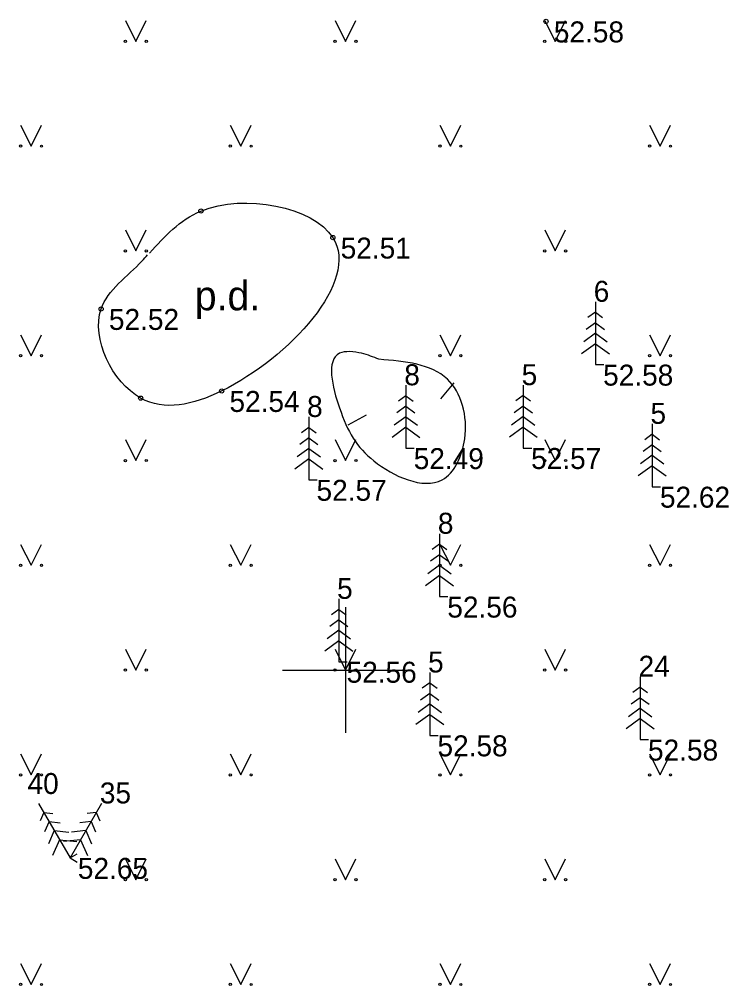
# Model space of a CAD drawing. Extents: x 619806 to 620082, y 405176 to 405386.
# Drawn here: x 619992.22 to 620009.14, y 405242.47 to 405265.53 of the extents above; entities that cross this region are included whole.
import ezdxf

# ---------------------------------------------------------------- set-up
doc = ezdxf.new("R2010")
doc.units = 0
for name, color, linetype in [('GEOD_ELEM_####_####_#', 7, 'Continuous'), ('RELJ_AATZ_####_TKST_#', 7, 'Continuous'), ('RELJ_ELEM_####_####_#', 7, 'Continuous'), ('RELJ_HORZ_PAMT_####_#', 7, 'Continuous'), ('TERT_DIAM_####_TKST_#', 7, 'Continuous'), ('TERT_ELEM_####_####_#', 7, 'Continuous'), ('TERT_IZMT_####_TKST_#', 7, 'Continuous'), ('TERT_KONT_####_####_#', 7, 'Continuous')]:
    doc.layers.add(name, color=color, linetype=linetype)

msp = doc.modelspace()

# ---------------------------------------------------------------- linework, layer by layer
at = {"layer": 'GEOD_ELEM_####_####_#'}
for p, q in [((620000, 405251.5), (620000, 405250)), ((619998.5, 405250), (620000, 405250)), ((620000, 405250), (620000, 405248.5)), ((620000, 405250), (620001.5, 405250))]:
    msp.add_line(p, q, dxfattribs=at)
at = {"layer": 'RELJ_ELEM_####_####_#'}
for centre in [(620004.782, 405265.475), (619996.552, 405260.952), (619999.699, 405260.318), (619994.172, 405258.616), (619997.047, 405256.659), (619995.114, 405256.488)]:
    msp.add_circle(centre, 0.05, dxfattribs=at)
at = {"layer": 'RELJ_HORZ_PAMT_####_#'}
for p, q in [((620002.276, 405256.47), (620002.593, 405256.856)), ((620000.493, 405256.08), (620000.052, 405255.845))]:
    msp.add_line(p, q, dxfattribs=at)
msp.add_spline([(620000.795, 405257.414), (620002.43, 405256.942), (620002.844, 405255.518), (620002.302, 405254.538), (620000.677, 405254.99), (619999.856, 405256.256), (619999.856, 405257.557), (620000.384, 405257.557), (620000.795, 405257.414)], degree=3, dxfattribs=at)
at = {"layer": 'TERT_ELEM_####_####_#'}
for p, q in [((619994.75, 405265.5), (619995, 405265)), ((619995, 405265), (619995.25, 405265.5)), ((619999.75, 405265.5), (620000, 405265)), ((620000, 405265), (620000.25, 405265.5)), ((620004.75, 405265.5), (620005, 405265)), ((620005, 405265), (620005.25, 405265.5)), ((619992.25, 405263), (619992.5, 405262.5)), ((619992.5, 405262.5), (619992.75, 405263)), ((619997.25, 405263), (619997.5, 405262.5)), ((619997.5, 405262.5), (619997.75, 405263)), ((620002.25, 405263), (620002.5, 405262.5)), ((620002.5, 405262.5), (620002.75, 405263)), ((620007.25, 405263), (620007.5, 405262.5)), ((620007.5, 405262.5), (620007.75, 405263)), ((619994.75, 405260.5), (619995, 405260)), ((619995, 405260), (619995.25, 405260.5)), ((620004.75, 405260.5), (620005, 405260)), ((620005, 405260), (620005.25, 405260.5)), ((620005.958, 405258.787), (620005.958, 405257.287)), ((620005.958, 405258.537), (620005.782, 405258.409)), ((620005.958, 405258.537), (620006.132, 405258.409)), ((620005.958, 405258.287), (620005.742, 405258.129)), ((620005.958, 405258.287), (620006.174, 405258.129)), ((619992.25, 405258), (619992.5, 405257.5)), ((619992.5, 405257.5), (619992.75, 405258)), ((620002.25, 405258), (620002.5, 405257.5)), ((620002.5, 405257.5), (620002.75, 405258)), ((620005.958, 405258.037), (620005.68, 405257.833)), ((620005.958, 405258.037), (620006.236, 405257.833)), ((620007.25, 405258), (620007.5, 405257.5)), ((620007.5, 405257.5), (620007.75, 405258)), ((620005.958, 405257.787), (620005.626, 405257.543)), ((620005.958, 405257.787), (620006.292, 405257.543)), ((620005.958, 405257.287), (620006.158, 405257.287)), ((620001.441, 405256.795), (620001.441, 405255.295)), ((620004.24, 405256.798), (620004.24, 405255.298)), ((620001.441, 405256.545), (620001.265, 405256.417)), ((620001.441, 405256.545), (620001.615, 405256.417)), ((620004.24, 405256.548), (620004.064, 405256.42)), ((620004.24, 405256.548), (620004.414, 405256.42)), ((620001.441, 405256.295), (620001.225, 405256.137)), ((620001.441, 405256.295), (620001.657, 405256.137)), ((620004.24, 405256.298), (620004.024, 405256.14)), ((620004.24, 405256.298), (620004.456, 405256.14)), ((619999.123, 405256.039), (619999.123, 405254.539)), ((620001.441, 405256.045), (620001.163, 405255.841)), ((620001.441, 405256.045), (620001.719, 405255.841)), ((620004.24, 405256.048), (620003.962, 405255.844)), ((620004.24, 405256.048), (620004.518, 405255.844)), ((619999.123, 405255.789), (619998.947, 405255.661)), ((619999.123, 405255.789), (619999.297, 405255.661)), ((620001.441, 405255.795), (620001.109, 405255.551)), ((620001.441, 405255.795), (620001.775, 405255.551)), ((620004.24, 405255.798), (620003.908, 405255.554)), ((620004.24, 405255.798), (620004.574, 405255.554)), ((620007.312, 405255.875), (620007.312, 405254.375)), ((619994.75, 405255.5), (619995, 405255)), ((619995, 405255), (619995.25, 405255.5)), ((619999.123, 405255.539), (619998.907, 405255.381)), ((619999.123, 405255.539), (619999.339, 405255.381)), ((619999.75, 405255.5), (620000, 405255)), ((620000, 405255), (620000.25, 405255.5)), ((620004.75, 405255.5), (620005, 405255)), ((620005, 405255), (620005.25, 405255.5)), ((620007.312, 405255.625), (620007.136, 405255.497)), ((620007.312, 405255.625), (620007.486, 405255.497)), ((619999.123, 405255.289), (619998.845, 405255.085)), ((619999.123, 405255.289), (619999.401, 405255.085)), ((620001.441, 405255.295), (620001.641, 405255.295)), ((620004.24, 405255.298), (620004.44, 405255.298)), ((620007.312, 405255.375), (620007.096, 405255.217)), ((620007.312, 405255.375), (620007.528, 405255.217)), ((619999.123, 405255.039), (619998.791, 405254.795)), ((619999.123, 405255.039), (619999.457, 405254.795)), ((620007.312, 405255.125), (620007.034, 405254.921)), ((620007.312, 405255.125), (620007.59, 405254.921)), ((620007.312, 405254.875), (620006.98, 405254.631)), ((620007.312, 405254.875), (620007.646, 405254.631)), ((619999.123, 405254.539), (619999.323, 405254.539)), ((620007.312, 405254.375), (620007.512, 405254.375)), ((620002.242, 405253.253), (620002.242, 405251.753)), ((619992.25, 405253), (619992.5, 405252.5)), ((619992.5, 405252.5), (619992.75, 405253)), ((619997.25, 405253), (619997.5, 405252.5)), ((619997.5, 405252.5), (619997.75, 405253)), ((620002.242, 405253.003), (620002.066, 405252.875)), ((620002.242, 405253.003), (620002.416, 405252.875)), ((620002.25, 405253), (620002.5, 405252.5)), ((620002.5, 405252.5), (620002.75, 405253)), ((620007.25, 405253), (620007.5, 405252.5)), ((620007.5, 405252.5), (620007.75, 405253)), ((620002.242, 405252.753), (620002.026, 405252.595)), ((620002.242, 405252.753), (620002.458, 405252.595)), ((620002.242, 405252.503), (620001.964, 405252.299)), ((620002.242, 405252.503), (620002.52, 405252.299)), ((620002.242, 405252.253), (620001.91, 405252.009)), ((620002.242, 405252.253), (620002.576, 405252.009)), ((619999.839, 405251.699), (619999.839, 405250.199)), ((620002.242, 405251.753), (620002.442, 405251.753)), ((619999.839, 405251.449), (619999.663, 405251.321)), ((619999.839, 405251.449), (620000.013, 405251.321)), ((619999.839, 405251.199), (619999.623, 405251.041)), ((619999.839, 405251.199), (620000.055, 405251.041)), ((619999.839, 405250.949), (619999.561, 405250.745)), ((619999.839, 405250.949), (620000.117, 405250.745)), ((619999.839, 405250.699), (619999.507, 405250.455)), ((619999.839, 405250.699), (620000.173, 405250.455)), ((619994.75, 405250.5), (619995, 405250)), ((619995, 405250), (619995.25, 405250.5)), ((619999.75, 405250.5), (620000, 405250)), ((620000, 405250), (620000.25, 405250.5)), ((620004.75, 405250.5), (620005, 405250)), ((620005, 405250), (620005.25, 405250.5)), ((619999.839, 405250.199), (620000.039, 405250.199)), ((620002.008, 405249.943), (620002.008, 405248.443)), ((620002.008, 405249.693), (620001.832, 405249.565)), ((620002.008, 405249.693), (620002.182, 405249.565)), ((620007.028, 405249.842), (620007.028, 405248.342)), ((620007.028, 405249.592), (620006.852, 405249.464)), ((620007.028, 405249.592), (620007.202, 405249.464)), ((620002.008, 405249.443), (620001.792, 405249.285)), ((620002.008, 405249.443), (620002.224, 405249.285)), ((620007.028, 405249.342), (620006.812, 405249.184)), ((620007.028, 405249.342), (620007.244, 405249.184)), ((620002.008, 405249.193), (620001.73, 405248.989)), ((620002.008, 405249.193), (620002.286, 405248.989)), ((620007.028, 405249.092), (620006.75, 405248.888)), ((620007.028, 405249.092), (620007.306, 405248.888)), ((620002.008, 405248.943), (620001.676, 405248.699)), ((620002.008, 405248.943), (620002.342, 405248.699)), ((620007.028, 405248.842), (620006.696, 405248.598)), ((620007.028, 405248.842), (620007.362, 405248.598)), ((620002.008, 405248.443), (620002.208, 405248.443)), ((620007.028, 405248.342), (620007.228, 405248.342)), ((619992.25, 405248), (619992.5, 405247.5)), ((619992.5, 405247.5), (619992.75, 405248)), ((619997.25, 405248), (619997.5, 405247.5)), ((619997.5, 405247.5), (619997.75, 405248)), ((620002.25, 405248), (620002.5, 405247.5)), ((620002.5, 405247.5), (620002.75, 405248)), ((620007.25, 405248), (620007.5, 405247.5)), ((620007.5, 405247.5), (620007.75, 405248)), ((619992.681, 405246.819), (619993.431, 405245.52)), ((619994.181, 405246.819), (619993.431, 405245.52)), ((619992.806, 405246.603), (619992.718, 405246.404)), ((619992.806, 405246.603), (619993.021, 405246.579)), ((619994.056, 405246.603), (619993.84, 405246.58)), ((619994.056, 405246.603), (619994.143, 405246.405)), ((619992.931, 405246.386), (619992.823, 405246.141)), ((619992.931, 405246.386), (619993.197, 405246.357)), ((619993.931, 405246.386), (619993.665, 405246.357)), ((619993.931, 405246.386), (619994.039, 405246.141)), ((619993.056, 405246.17), (619992.917, 405245.854)), ((619993.056, 405246.17), (619993.399, 405246.132)), ((619993.806, 405246.17), (619993.463, 405246.132)), ((619993.806, 405246.17), (619993.945, 405245.854)), ((619993.181, 405245.953), (619993.015, 405245.576)), ((619993.181, 405245.953), (619993.592, 405245.909)), ((619993.681, 405245.953), (619993.271, 405245.908)), ((619993.681, 405245.953), (619993.848, 405245.575)), ((619993.431, 405245.52), (619993.604, 405245.62)), ((619993.431, 405245.52), (619993.604, 405245.42)), ((619994.75, 405245.5), (619995, 405245)), ((619995, 405245), (619995.25, 405245.5)), ((619999.75, 405245.5), (620000, 405245)), ((620000, 405245), (620000.25, 405245.5)), ((620004.75, 405245.5), (620005, 405245)), ((620005, 405245), (620005.25, 405245.5)), ((619992.25, 405243), (619992.5, 405242.5)), ((619992.5, 405242.5), (619992.75, 405243)), ((619997.25, 405243), (619997.5, 405242.5)), ((619997.5, 405242.5), (619997.75, 405243)), ((620002.25, 405243), (620002.5, 405242.5)), ((620002.5, 405242.5), (620002.75, 405243)), ((620007.25, 405243), (620007.5, 405242.5)), ((620007.5, 405242.5), (620007.75, 405243))]:
    msp.add_line(p, q, dxfattribs=at)
for centre, radius in [((619994.75, 405265), 0.028), ((619995.25, 405265), 0.0263), ((619999.75, 405265), 0.028), ((620000.25, 405265), 0.0263), ((620004.75, 405265), 0.028), ((620005.25, 405265), 0.0263), ((619992.25, 405262.5), 0.028), ((619992.75, 405262.5), 0.0263), ((619997.25, 405262.5), 0.028), ((619997.75, 405262.5), 0.0263), ((620002.25, 405262.5), 0.028), ((620002.75, 405262.5), 0.0263), ((620007.25, 405262.5), 0.028), ((620007.75, 405262.5), 0.0263), ((619994.75, 405260), 0.028), ((619995.25, 405260), 0.0263), ((620004.75, 405260), 0.028), ((620005.25, 405260), 0.0263), ((619992.25, 405257.5), 0.028), ((619992.75, 405257.5), 0.0263), ((620002.25, 405257.5), 0.028), ((620002.75, 405257.5), 0.0263), ((620007.25, 405257.5), 0.028), ((620007.75, 405257.5), 0.0263), ((619994.75, 405255), 0.028), ((619995.25, 405255), 0.0263), ((619999.75, 405255), 0.028), ((620000.25, 405255), 0.0263), ((620004.75, 405255), 0.028), ((620005.25, 405255), 0.0263), ((619992.25, 405252.5), 0.028), ((619992.75, 405252.5), 0.0263), ((619997.25, 405252.5), 0.028), ((619997.75, 405252.5), 0.0263), ((620002.25, 405252.5), 0.028), ((620002.75, 405252.5), 0.0263), ((620007.25, 405252.5), 0.028), ((620007.75, 405252.5), 0.0263), ((619994.75, 405250), 0.028), ((619995.25, 405250), 0.0263), ((619999.75, 405250), 0.028), ((620000.25, 405250), 0.0263), ((620004.75, 405250), 0.028), ((620005.25, 405250), 0.0263), ((619992.25, 405247.5), 0.028), ((619992.75, 405247.5), 0.0263), ((619997.25, 405247.5), 0.028), ((619997.75, 405247.5), 0.0263), ((620002.25, 405247.5), 0.028), ((620002.75, 405247.5), 0.0263), ((620007.25, 405247.5), 0.028), ((620007.75, 405247.5), 0.0263), ((619994.75, 405245), 0.028), ((619995.25, 405245), 0.0263), ((619999.75, 405245), 0.028), ((620000.25, 405245), 0.0263), ((620004.75, 405245), 0.028), ((620005.25, 405245), 0.0263), ((619992.25, 405242.5), 0.028), ((619992.75, 405242.5), 0.0263), ((619997.25, 405242.5), 0.028), ((619997.75, 405242.5), 0.0263), ((620002.25, 405242.5), 0.028), ((620002.75, 405242.5), 0.0263), ((620007.25, 405242.5), 0.028), ((620007.75, 405242.5), 0.0263)]:
    msp.add_circle(centre, radius, dxfattribs=at)
at = {"layer": 'TERT_KONT_####_####_#'}
msp.add_spline([(619995.329, 405259.95), (619996.552, 405260.952), (619999.699, 405260.318), (619997.047, 405256.659), (619995.114, 405256.488), (619994.172, 405258.616), (619995.148, 405259.76), (619995.282, 405259.908)], degree=3, dxfattribs=at)

# ---------------------------------------------------------------- texts
at = {"layer": 'RELJ_AATZ_####_TKST_#'}
for s, p in [(' 52.58', (620004.782, 405264.975)), (' 52.51', (619999.699, 405259.818)), (' 52.52', (619994.172, 405258.116)), (' 52.58', (620005.958, 405256.787)), (' 52.54', (619997.047, 405256.159)), (' 52.49', (620001.441, 405254.795)), (' 52.57', (620004.24, 405254.798)), (' 52.57', (619999.123, 405254.039)), (' 52.62', (620007.312, 405253.875)), (' 52.56', (620002.242, 405251.253)), (' 52.56', (619999.839, 405249.699)), (' 52.58', (620002.008, 405247.943)), (' 52.58', (620007.028, 405247.842)), (' 52.65', (619993.431, 405245.02))]:
    msp.add_text(s, height=0.5, dxfattribs=at).set_placement(p)
at = {"layer": 'TERT_DIAM_####_TKST_#'}
for s, p in [(' 6', (620005.733, 405258.787)), (' 8', (620001.216, 405256.795)), (' 5', (620004.015, 405256.798)), (' 8', (619998.898, 405256.039)), (' 5', (620007.087, 405255.875)), (' 8', (620002.017, 405253.253)), (' 5', (619999.614, 405251.699)), (' 5', (620001.783, 405249.943)), (' 24', (620006.803, 405249.842)), (' 40', (619992.231, 405247.044)), (' 35', (619993.956, 405246.819))]:
    msp.add_text(s, height=0.5, dxfattribs=at).set_placement(p)
at = {"layer": 'TERT_IZMT_####_TKST_#'}
msp.add_text('p.d.', height=0.7, dxfattribs=at).set_placement((619996.405, 405258.584))

doc.saveas('drawing.dxf')
